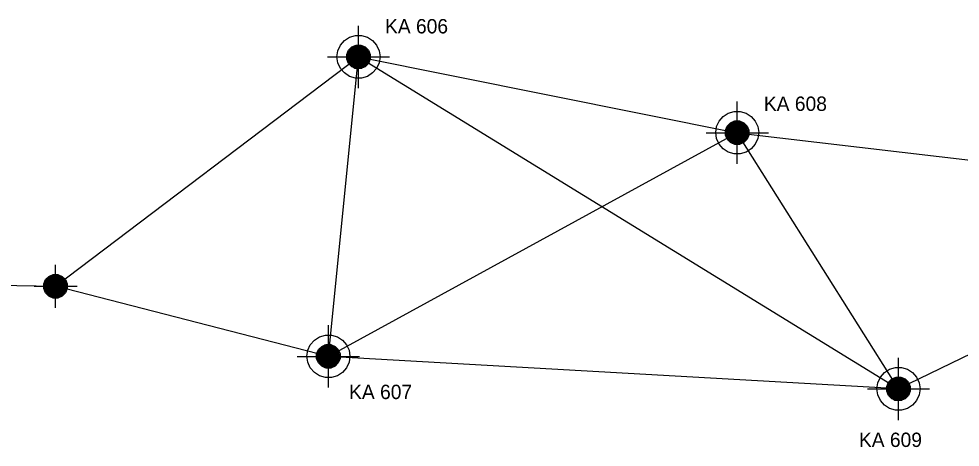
# Model space of a CAD drawing. Extents: x -346533 to -339969, y -1273090 to -1271585.
# Drawn here: x -341981.8 to -341490.3, y -1272131.7 to -1271908 of the extents above; entities that cross this region are included whole.
import ezdxf

# ---------------------------------------------------------------- set-up
doc = ezdxf.new("R2010")
doc.units = 0
for name, color, linetype in [('BP_11', 7, 'Continuous'), ('BP_12', 7, 'Continuous'), ('BP_14', 7, 'Continuous')]:
    doc.layers.add(name, color=color, linetype=linetype)

msp = doc.modelspace()

# ---------------------------------------------------------------- linework, layer by layer
at = {"layer": 'BP_11'}
for points in [[(-341804.43, -1271944.13), (-341804.43, -1271937.78), (-341804.43, -1271931.43), (-341804.43, -1271925.08), (-341804.43, -1271918.73), (-341804.43, -1271912.38), (-341804.43, -1271911.63)], [(-341804.43, -1271921.73), (-341803.23, -1271921.73), (-341800.98, -1271922.68), (-341799.28, -1271924.38), (-341798.33, -1271926.63), (-341798.33, -1271929.08), (-341799.28, -1271931.33), (-341800.98, -1271933.03), (-341803.23, -1271933.98), (-341805.68, -1271933.98), (-341807.93, -1271933.03), (-341809.63, -1271931.33), (-341810.58, -1271929.08), (-341810.58, -1271926.63), (-341809.63, -1271924.38), (-341807.93, -1271922.68), (-341805.68, -1271921.73), (-341804.48, -1271921.73), (-341802.68, -1271922.08), (-341806.28, -1271922.08), (-341807.08, -1271922.48), (-341801.88, -1271922.48), (-341801.08, -1271922.88), (-341807.43, -1271922.88), (-341807.88, -1271922.88), (-341808.28, -1271923.28), (-341801.93, -1271923.28), (-341800.68, -1271923.28), (-341800.28, -1271923.68), (-341806.63, -1271923.68), (-341808.68, -1271923.68), (-341809.08, -1271924.08), (-341802.73, -1271924.08), (-341799.88, -1271924.08), (-341799.48, -1271924.48), (-341805.83, -1271924.48), (-341809.48, -1271924.48), (-341809.48, -1271924.88), (-341803.13, -1271924.88), (-341799.48, -1271924.88), (-341799.08, -1271925.28), (-341805.43, -1271925.28), (-341809.88, -1271925.28), (-341809.88, -1271925.68), (-341803.53, -1271925.68), (-341799.08, -1271925.68), (-341799.08, -1271926.08), (-341805.43, -1271926.08), (-341809.88, -1271926.08), (-341810.28, -1271926.48), (-341803.93, -1271926.48), (-341798.68, -1271926.48), (-341798.68, -1271926.88), (-341805.03, -1271926.88), (-341810.28, -1271926.88), (-341810.28, -1271927.28), (-341803.93, -1271927.28), (-341798.68, -1271927.28), (-341798.68, -1271927.68), (-341805.03, -1271927.68), (-341810.28, -1271927.68), (-341810.28, -1271928.08), (-341803.93, -1271928.08), (-341798.68, -1271928.08), (-341798.68, -1271928.48), (-341805.03, -1271928.48), (-341810.28, -1271928.48), (-341810.28, -1271928.88), (-341803.93, -1271928.88), (-341798.68, -1271928.88), (-341798.68, -1271929.28), (-341805.03, -1271929.28), (-341810.28, -1271929.28), (-341810.28, -1271929.68), (-341803.93, -1271929.68), (-341798.68, -1271929.68), (-341799.08, -1271930.08), (-341805.43, -1271930.08), (-341809.88, -1271930.08), (-341809.88, -1271930.48), (-341803.53, -1271930.48), (-341799.08, -1271930.48), (-341799.48, -1271930.88), (-341805.83, -1271930.88), (-341809.48, -1271930.88), (-341809.48, -1271931.28), (-341803.13, -1271931.28), (-341799.48, -1271931.28), (-341799.88, -1271931.68), (-341806.23, -1271931.68), (-341809.08, -1271931.68), (-341808.68, -1271932.08), (-341802.33, -1271932.08), (-341800.28, -1271932.08), (-341800.68, -1271932.48), (-341807.03, -1271932.48), (-341808.28, -1271932.48), (-341807.88, -1271932.88), (-341801.53, -1271932.88), (-341801.08, -1271932.88)], [(-341820.68, -1271927.88), (-341814.33, -1271927.88), (-341807.98, -1271927.88), (-341801.63, -1271927.88), (-341795.28, -1271927.88), (-341788.93, -1271927.88), (-341788.18, -1271927.88)], [(-341801.08, -1271932.88), (-341801.88, -1271933.28), (-341807.08, -1271933.28), (-341806.28, -1271933.68), (-341802.68, -1271933.68)], [(-341606.7, -1271983.73), (-341606.7, -1271977.38), (-341606.7, -1271971.03), (-341606.7, -1271964.68), (-341606.7, -1271958.33), (-341606.7, -1271951.98), (-341606.7, -1271951.23)], [(-341606.7, -1271961.33), (-341605.5, -1271961.33), (-341603.25, -1271962.28), (-341601.55, -1271963.98), (-341600.6, -1271966.23), (-341600.6, -1271968.68), (-341601.55, -1271970.93), (-341603.25, -1271972.63), (-341605.5, -1271973.58), (-341607.95, -1271973.58), (-341610.2, -1271972.63), (-341611.9, -1271970.93), (-341612.85, -1271968.68), (-341612.85, -1271966.23), (-341611.9, -1271963.98), (-341610.2, -1271962.28), (-341607.95, -1271961.33), (-341606.75, -1271961.33), (-341604.95, -1271961.68), (-341608.55, -1271961.68), (-341609.35, -1271962.08), (-341604.15, -1271962.08), (-341603.35, -1271962.48), (-341609.7, -1271962.48), (-341610.15, -1271962.48), (-341610.55, -1271962.88), (-341604.2, -1271962.88), (-341602.95, -1271962.88), (-341602.55, -1271963.28), (-341608.9, -1271963.28), (-341610.95, -1271963.28), (-341611.35, -1271963.68), (-341605, -1271963.68), (-341602.15, -1271963.68), (-341601.75, -1271964.08), (-341608.1, -1271964.08), (-341611.75, -1271964.08), (-341611.75, -1271964.48), (-341605.4, -1271964.48), (-341601.75, -1271964.48), (-341601.35, -1271964.88), (-341607.7, -1271964.88), (-341612.15, -1271964.88), (-341612.15, -1271965.28), (-341605.8, -1271965.28), (-341601.35, -1271965.28), (-341601.35, -1271965.68), (-341607.7, -1271965.68), (-341612.15, -1271965.68), (-341612.55, -1271966.08), (-341606.2, -1271966.08), (-341600.95, -1271966.08), (-341600.95, -1271966.48), (-341607.3, -1271966.48), (-341612.55, -1271966.48), (-341612.55, -1271966.88), (-341606.2, -1271966.88), (-341600.95, -1271966.88), (-341600.95, -1271967.28), (-341607.3, -1271967.28), (-341612.55, -1271967.28), (-341612.55, -1271967.68), (-341606.2, -1271967.68), (-341600.95, -1271967.68), (-341600.95, -1271968.08), (-341607.3, -1271968.08), (-341612.55, -1271968.08), (-341612.55, -1271968.48), (-341606.2, -1271968.48), (-341600.95, -1271968.48), (-341600.95, -1271968.88), (-341607.3, -1271968.88), (-341612.55, -1271968.88), (-341612.55, -1271969.28), (-341606.2, -1271969.28), (-341600.95, -1271969.28), (-341601.35, -1271969.68), (-341607.7, -1271969.68), (-341612.15, -1271969.68), (-341612.15, -1271970.08), (-341605.8, -1271970.08), (-341601.35, -1271970.08), (-341601.75, -1271970.48), (-341608.1, -1271970.48), (-341611.75, -1271970.48), (-341611.75, -1271970.88), (-341605.4, -1271970.88), (-341601.75, -1271970.88), (-341602.15, -1271971.28), (-341608.5, -1271971.28), (-341611.35, -1271971.28), (-341610.95, -1271971.68), (-341604.6, -1271971.68), (-341602.55, -1271971.68), (-341602.95, -1271972.08), (-341609.3, -1271972.08), (-341610.55, -1271972.08), (-341610.15, -1271972.48), (-341603.8, -1271972.48), (-341603.35, -1271972.48)], [(-341622.95, -1271967.48), (-341616.6, -1271967.48), (-341610.25, -1271967.48), (-341603.9, -1271967.48), (-341597.55, -1271967.48), (-341591.2, -1271967.48), (-341590.45, -1271967.48)], [(-341603.35, -1271972.48), (-341604.15, -1271972.88), (-341609.35, -1271972.88), (-341608.55, -1271973.28), (-341604.95, -1271973.28)], [(-341962.56, -1272058.96), (-341962.56, -1272052.61), (-341962.56, -1272046.26), (-341962.56, -1272039.91), (-341962.56, -1272036.46)], [(-341962.56, -1272041.56), (-341961.36, -1272041.56), (-341959.11, -1272042.51), (-341957.41, -1272044.21), (-341956.46, -1272046.46), (-341956.46, -1272048.91), (-341957.41, -1272051.16), (-341959.11, -1272052.86), (-341961.36, -1272053.81), (-341963.81, -1272053.81), (-341966.06, -1272052.86), (-341967.76, -1272051.16), (-341968.71, -1272048.91), (-341968.71, -1272046.46), (-341967.76, -1272044.21), (-341966.06, -1272042.51), (-341963.81, -1272041.56), (-341962.61, -1272041.56), (-341960.81, -1272041.91), (-341964.41, -1272041.91), (-341965.21, -1272042.31), (-341960.01, -1272042.31), (-341959.21, -1272042.71), (-341965.56, -1272042.71), (-341966.01, -1272042.71), (-341966.41, -1272043.11), (-341960.06, -1272043.11), (-341958.81, -1272043.11), (-341958.41, -1272043.51), (-341964.76, -1272043.51), (-341966.81, -1272043.51), (-341967.21, -1272043.91), (-341960.86, -1272043.91), (-341958.01, -1272043.91), (-341957.61, -1272044.31), (-341963.96, -1272044.31), (-341967.61, -1272044.31), (-341967.61, -1272044.71), (-341961.26, -1272044.71), (-341957.61, -1272044.71), (-341957.21, -1272045.11), (-341963.56, -1272045.11), (-341968.01, -1272045.11), (-341968.01, -1272045.51), (-341961.66, -1272045.51), (-341957.21, -1272045.51), (-341956.81, -1272045.91), (-341963.16, -1272045.91), (-341968.41, -1272045.91), (-341968.41, -1272046.31), (-341962.06, -1272046.31), (-341956.81, -1272046.31), (-341956.81, -1272046.71), (-341963.16, -1272046.71), (-341968.41, -1272046.71), (-341968.41, -1272047.11), (-341962.06, -1272047.11), (-341956.81, -1272047.11), (-341956.81, -1272047.51), (-341963.16, -1272047.51), (-341968.41, -1272047.51), (-341968.41, -1272047.91), (-341962.06, -1272047.91), (-341956.81, -1272047.91), (-341956.81, -1272048.31), (-341963.16, -1272048.31), (-341968.41, -1272048.31), (-341968.41, -1272048.71), (-341962.06, -1272048.71), (-341956.81, -1272048.71), (-341956.81, -1272049.11), (-341963.16, -1272049.11), (-341968.41, -1272049.11), (-341968.41, -1272049.51), (-341962.06, -1272049.51), (-341956.81, -1272049.51), (-341957.21, -1272049.91), (-341963.56, -1272049.91), (-341968.01, -1272049.91), (-341968.01, -1272050.31), (-341961.66, -1272050.31), (-341957.21, -1272050.31), (-341957.61, -1272050.71), (-341963.96, -1272050.71), (-341967.61, -1272050.71), (-341967.61, -1272051.11), (-341961.26, -1272051.11), (-341957.61, -1272051.11), (-341958.01, -1272051.51), (-341964.36, -1272051.51), (-341967.21, -1272051.51), (-341966.81, -1272051.91), (-341960.46, -1272051.91), (-341958.41, -1272051.91), (-341958.81, -1272052.31), (-341965.16, -1272052.31), (-341966.41, -1272052.31), (-341966.01, -1272052.71), (-341959.66, -1272052.71), (-341959.21, -1272052.71)], [(-341973.81, -1272047.71), (-341967.46, -1272047.71), (-341961.11, -1272047.71), (-341954.76, -1272047.71), (-341951.31, -1272047.71)], [(-341959.21, -1272052.71), (-341960.01, -1272053.11), (-341965.21, -1272053.11), (-341964.41, -1272053.51), (-341960.81, -1272053.51)], [(-341820.13, -1272100.53), (-341820.13, -1272094.18), (-341820.13, -1272087.83), (-341820.13, -1272081.48), (-341820.13, -1272075.13), (-341820.13, -1272068.78), (-341820.13, -1272068.03)], [(-341820.13, -1272078.13), (-341818.93, -1272078.13), (-341816.68, -1272079.08), (-341814.98, -1272080.78), (-341814.03, -1272083.03), (-341814.03, -1272085.48), (-341814.98, -1272087.73), (-341816.68, -1272089.43), (-341818.93, -1272090.38), (-341821.38, -1272090.38), (-341823.63, -1272089.43), (-341825.33, -1272087.73), (-341826.28, -1272085.48), (-341826.28, -1272083.03), (-341825.33, -1272080.78), (-341823.63, -1272079.08), (-341821.38, -1272078.13), (-341820.18, -1272078.13), (-341818.38, -1272078.48), (-341821.98, -1272078.48), (-341822.78, -1272078.88), (-341817.58, -1272078.88), (-341816.78, -1272079.28), (-341823.13, -1272079.28), (-341823.58, -1272079.28), (-341823.98, -1272079.68), (-341817.63, -1272079.68), (-341816.38, -1272079.68), (-341815.98, -1272080.08), (-341822.33, -1272080.08), (-341824.38, -1272080.08), (-341824.78, -1272080.48), (-341818.43, -1272080.48), (-341815.58, -1272080.48), (-341815.18, -1272080.88), (-341821.53, -1272080.88), (-341825.18, -1272080.88), (-341825.18, -1272081.28), (-341818.83, -1272081.28), (-341815.18, -1272081.28), (-341814.78, -1272081.68), (-341821.13, -1272081.68), (-341825.58, -1272081.68), (-341825.58, -1272082.08), (-341819.23, -1272082.08), (-341814.78, -1272082.08), (-341814.78, -1272082.48), (-341821.13, -1272082.48), (-341825.58, -1272082.48), (-341825.98, -1272082.88), (-341819.63, -1272082.88), (-341814.38, -1272082.88), (-341814.38, -1272083.28), (-341820.73, -1272083.28), (-341825.98, -1272083.28), (-341825.98, -1272083.68), (-341819.63, -1272083.68), (-341814.38, -1272083.68), (-341814.38, -1272084.08), (-341820.73, -1272084.08), (-341825.98, -1272084.08), (-341825.98, -1272084.48), (-341819.63, -1272084.48), (-341814.38, -1272084.48), (-341814.38, -1272084.88), (-341820.73, -1272084.88), (-341825.98, -1272084.88), (-341825.98, -1272085.28), (-341819.63, -1272085.28), (-341814.38, -1272085.28), (-341814.38, -1272085.68), (-341820.73, -1272085.68), (-341825.98, -1272085.68), (-341825.98, -1272086.08), (-341819.63, -1272086.08), (-341814.38, -1272086.08), (-341814.78, -1272086.48), (-341821.13, -1272086.48), (-341825.58, -1272086.48), (-341825.58, -1272086.88), (-341819.23, -1272086.88), (-341814.78, -1272086.88), (-341815.18, -1272087.28), (-341821.53, -1272087.28), (-341825.18, -1272087.28), (-341825.18, -1272087.68), (-341818.83, -1272087.68), (-341815.18, -1272087.68), (-341815.58, -1272088.08), (-341821.93, -1272088.08), (-341824.78, -1272088.08), (-341824.38, -1272088.48), (-341818.03, -1272088.48), (-341815.98, -1272088.48), (-341816.38, -1272088.88), (-341822.73, -1272088.88), (-341823.98, -1272088.88), (-341823.58, -1272089.28), (-341817.23, -1272089.28), (-341816.78, -1272089.28)], [(-341836.38, -1272084.28), (-341830.03, -1272084.28), (-341823.68, -1272084.28), (-341817.33, -1272084.28), (-341810.98, -1272084.28), (-341804.63, -1272084.28), (-341803.88, -1272084.28)], [(-341816.78, -1272089.28), (-341817.58, -1272089.68), (-341822.78, -1272089.68), (-341821.98, -1272090.08), (-341818.38, -1272090.08)], [(-341522.51, -1272117.55), (-341522.51, -1272111.2), (-341522.51, -1272104.85), (-341522.51, -1272098.5), (-341522.51, -1272092.15), (-341522.51, -1272085.8), (-341522.51, -1272085.05)], [(-341522.51, -1272095.15), (-341521.31, -1272095.15), (-341519.06, -1272096.1), (-341517.36, -1272097.8), (-341516.41, -1272100.05), (-341516.41, -1272102.5), (-341517.36, -1272104.75), (-341519.06, -1272106.45), (-341521.31, -1272107.4), (-341523.76, -1272107.4), (-341526.01, -1272106.45), (-341527.71, -1272104.75), (-341528.66, -1272102.5), (-341528.66, -1272100.05), (-341527.71, -1272097.8), (-341526.01, -1272096.1), (-341523.76, -1272095.15), (-341522.56, -1272095.15), (-341520.76, -1272095.5), (-341524.36, -1272095.5), (-341525.16, -1272095.9), (-341519.96, -1272095.9), (-341519.16, -1272096.3), (-341525.51, -1272096.3), (-341525.96, -1272096.3), (-341526.36, -1272096.7), (-341520.01, -1272096.7), (-341518.76, -1272096.7), (-341518.36, -1272097.1), (-341524.71, -1272097.1), (-341526.76, -1272097.1), (-341527.16, -1272097.5), (-341520.81, -1272097.5), (-341517.96, -1272097.5), (-341517.56, -1272097.9), (-341523.91, -1272097.9), (-341527.56, -1272097.9), (-341527.56, -1272098.3), (-341521.21, -1272098.3), (-341517.56, -1272098.3), (-341517.16, -1272098.7), (-341523.51, -1272098.7), (-341527.96, -1272098.7), (-341527.96, -1272099.1), (-341521.61, -1272099.1), (-341517.16, -1272099.1), (-341517.16, -1272099.5), (-341523.51, -1272099.5), (-341527.96, -1272099.5), (-341528.36, -1272099.9), (-341522.01, -1272099.9), (-341516.76, -1272099.9), (-341516.76, -1272100.3), (-341523.11, -1272100.3), (-341528.36, -1272100.3), (-341528.36, -1272100.7), (-341522.01, -1272100.7), (-341516.76, -1272100.7), (-341516.76, -1272101.1), (-341523.11, -1272101.1), (-341528.36, -1272101.1), (-341528.36, -1272101.5), (-341522.01, -1272101.5), (-341516.76, -1272101.5), (-341516.76, -1272101.9), (-341523.11, -1272101.9), (-341528.36, -1272101.9), (-341528.36, -1272102.3), (-341522.01, -1272102.3), (-341516.76, -1272102.3), (-341516.76, -1272102.7), (-341523.11, -1272102.7), (-341528.36, -1272102.7), (-341528.36, -1272103.1), (-341522.01, -1272103.1), (-341516.76, -1272103.1), (-341517.16, -1272103.5), (-341523.51, -1272103.5), (-341527.96, -1272103.5), (-341527.96, -1272103.9), (-341521.61, -1272103.9), (-341517.16, -1272103.9), (-341517.56, -1272104.3), (-341523.91, -1272104.3), (-341527.56, -1272104.3), (-341527.56, -1272104.7), (-341521.21, -1272104.7), (-341517.56, -1272104.7), (-341517.96, -1272105.1), (-341524.31, -1272105.1), (-341527.16, -1272105.1), (-341526.76, -1272105.5), (-341520.41, -1272105.5), (-341518.36, -1272105.5), (-341518.76, -1272105.9), (-341525.11, -1272105.9), (-341526.36, -1272105.9), (-341525.96, -1272106.3), (-341519.61, -1272106.3), (-341519.16, -1272106.3)], [(-341538.76, -1272101.3), (-341532.41, -1272101.3), (-341526.06, -1272101.3), (-341519.71, -1272101.3), (-341513.36, -1272101.3), (-341507.01, -1272101.3), (-341506.26, -1272101.3)], [(-341519.16, -1272106.3), (-341519.96, -1272106.7), (-341525.16, -1272106.7), (-341524.36, -1272107.1), (-341520.76, -1272107.1)]]:
    msp.add_lwpolyline(points, dxfattribs=at)
for points in [[(-341802.83, -1271916.73), (-341799.78, -1271917.63), (-341797.08, -1271919.38), (-341794.98, -1271921.78), (-341793.63, -1271924.68), (-341793.18, -1271927.83), (-341793.63, -1271930.98), (-341794.98, -1271933.88), (-341797.08, -1271936.28), (-341799.78, -1271938.03), (-341802.83, -1271938.93), (-341806.03, -1271938.93), (-341809.08, -1271938.03), (-341811.78, -1271936.28), (-341813.88, -1271933.88), (-341815.23, -1271930.98), (-341815.68, -1271927.83), (-341815.23, -1271924.68), (-341813.88, -1271921.78), (-341811.78, -1271919.38), (-341809.08, -1271917.63), (-341806.03, -1271916.73)], [(-341605.1, -1271956.33), (-341602.05, -1271957.23), (-341599.35, -1271958.98), (-341597.25, -1271961.38), (-341595.9, -1271964.28), (-341595.45, -1271967.43), (-341595.9, -1271970.58), (-341597.25, -1271973.48), (-341599.35, -1271975.88), (-341602.05, -1271977.63), (-341605.1, -1271978.53), (-341608.3, -1271978.53), (-341611.35, -1271977.63), (-341614.05, -1271975.88), (-341616.15, -1271973.48), (-341617.5, -1271970.58), (-341617.95, -1271967.43), (-341617.5, -1271964.28), (-341616.15, -1271961.38), (-341614.05, -1271958.98), (-341611.35, -1271957.23), (-341608.3, -1271956.33)], [(-341961.36, -1272041.56), (-341959.11, -1272042.51), (-341957.41, -1272044.21), (-341956.46, -1272046.46), (-341956.46, -1272048.91), (-341957.41, -1272051.16), (-341959.11, -1272052.86), (-341961.36, -1272053.81), (-341963.81, -1272053.81), (-341966.06, -1272052.86), (-341967.76, -1272051.16), (-341968.71, -1272048.91), (-341968.71, -1272046.46), (-341967.76, -1272044.21), (-341966.06, -1272042.51), (-341963.81, -1272041.56)], [(-341818.53, -1272073.13), (-341815.48, -1272074.03), (-341812.78, -1272075.78), (-341810.68, -1272078.18), (-341809.33, -1272081.08), (-341808.88, -1272084.23), (-341809.33, -1272087.38), (-341810.68, -1272090.28), (-341812.78, -1272092.68), (-341815.48, -1272094.43), (-341818.53, -1272095.33), (-341821.73, -1272095.33), (-341824.78, -1272094.43), (-341827.48, -1272092.68), (-341829.58, -1272090.28), (-341830.93, -1272087.38), (-341831.38, -1272084.23), (-341830.93, -1272081.08), (-341829.58, -1272078.18), (-341827.48, -1272075.78), (-341824.78, -1272074.03), (-341821.73, -1272073.13)], [(-341520.91, -1272090.15), (-341517.86, -1272091.05), (-341515.16, -1272092.8), (-341513.06, -1272095.2), (-341511.71, -1272098.1), (-341511.26, -1272101.25), (-341511.71, -1272104.4), (-341513.06, -1272107.3), (-341515.16, -1272109.7), (-341517.86, -1272111.45), (-341520.91, -1272112.35), (-341524.11, -1272112.35), (-341527.16, -1272111.45), (-341529.86, -1272109.7), (-341531.96, -1272107.3), (-341533.31, -1272104.4), (-341533.76, -1272101.25), (-341533.31, -1272098.1), (-341531.96, -1272095.2), (-341529.86, -1272092.8), (-341527.16, -1272091.05), (-341524.11, -1272090.15)]]:
    msp.add_lwpolyline(points, close=True, dxfattribs=at)
at = {"layer": 'BP_14'}
for p, q in [((-341962.56, -1272047.71), (-341804.43, -1271927.88)), ((-341820.13, -1272084.28), (-341804.43, -1271927.88)), ((-341804.43, -1271927.88), (-341606.7, -1271967.48)), ((-341804.43, -1271927.88), (-341522.51, -1272101.3)), ((-341606.7, -1271967.48), (-341820.13, -1272084.28)), ((-341606.7, -1271967.48), (-341317.45, -1272001.62)), ((-341522.51, -1272101.3), (-341606.7, -1271967.48)), ((-341317.45, -1272001.62), (-341522.51, -1272101.3)), ((-342169.95, -1272043.36), (-341962.56, -1272047.71)), ((-341820.13, -1272084.28), (-341962.56, -1272047.71)), ((-341522.51, -1272101.3), (-341820.13, -1272084.28))]:
    msp.add_line(p, q, dxfattribs=at)

# ---------------------------------------------------------------- texts
at = {"layer": 'BP_12'}
for s, p in [('KA 606', (-341790.58, -1271915.6)), ('KA 608', (-341592.78, -1271956.08)), ('KA 607', (-341809.34, -1272106.59)), ('KA 609', (-341543.15, -1272131.62))]:
    msp.add_text(s, height=7.5, dxfattribs=at).set_placement(p)

doc.saveas('drawing.dxf')
